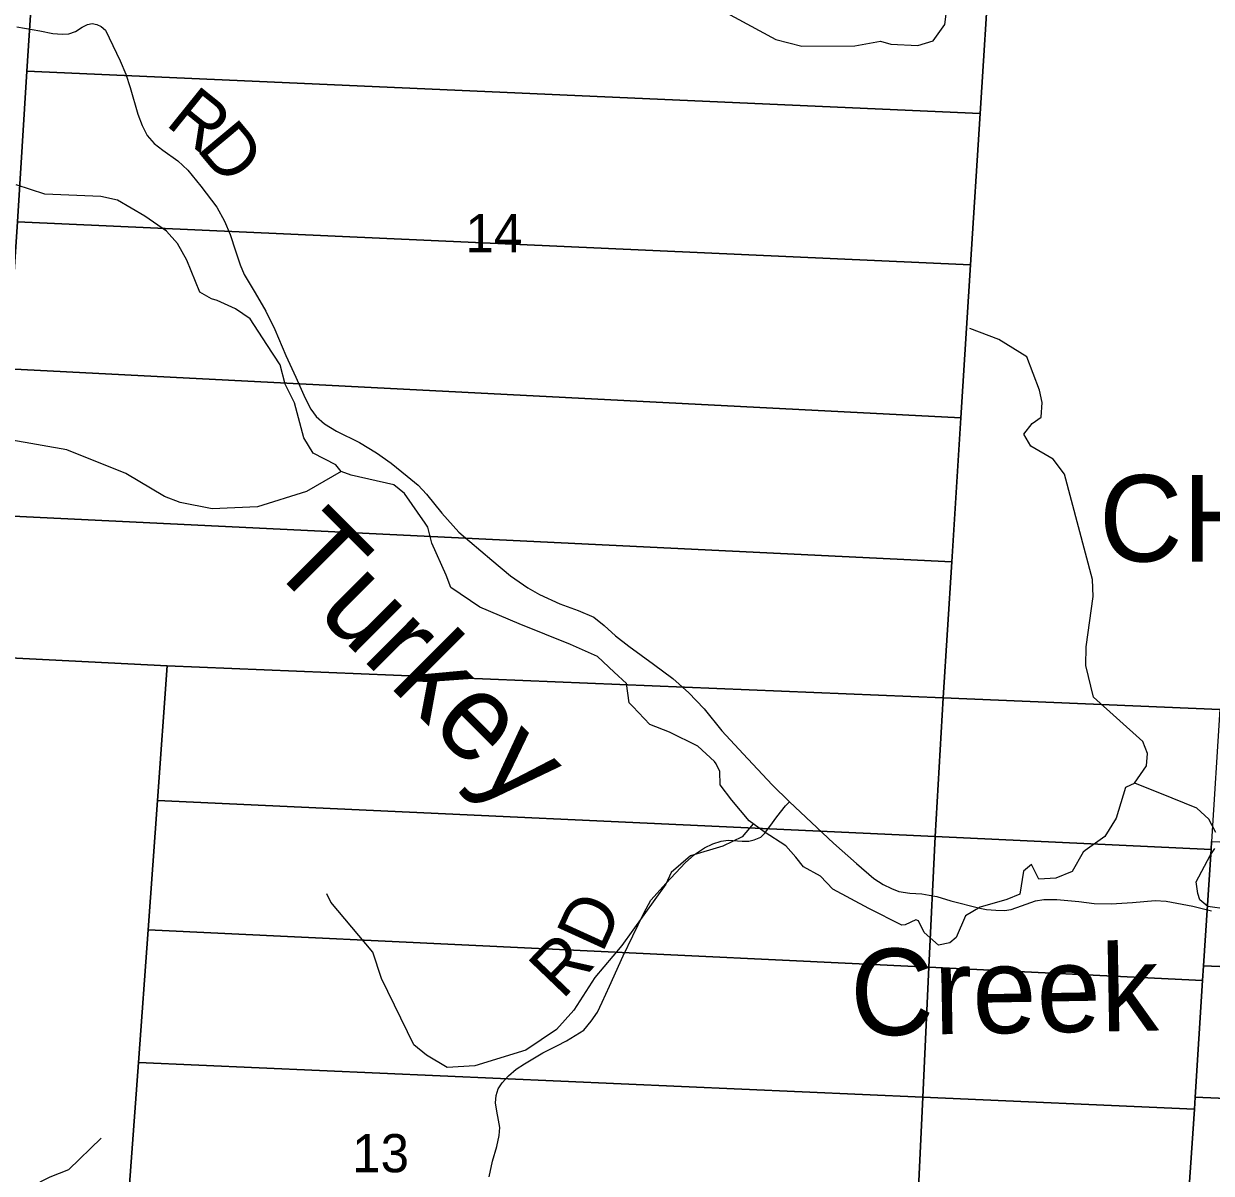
# Model space of a CAD drawing. Extents: x 1878108 to 2183446, y 146837 to 508383.
# Drawn here: x 2065694 to 2072564, y 342011 to 348659 of the extents above; entities that cross this region are included whole.
import ezdxf

# ---------------------------------------------------------------- set-up
doc = ezdxf.new("R2010")
doc.units = 0
for name, color, linetype in [('GM_X_Corporation_Text', 7, 'Continuous'), ('GM_X_Minor_River', 7, 'Continuous'), ('GM_X_Minor_River_Text', 7, 'Continuous'), ('GM_X_Section', 7, 'Continuous'), ('GM_X_Section_Text', 7, 'Continuous'), ('GM_X_Township_Road', 7, 'Continuous'), ('GM_X_Township_Road_Text', 7, 'Continuous')]:
    doc.layers.add(name, color=color, linetype=linetype)

msp = doc.modelspace()

# ---------------------------------------------------------------- linework, layer by layer
at = {"layer": 'GM_X_Minor_River'}
for points in [[(2069733.7, 348736.5), (2070045.5, 348568.4), (2070195.6, 348529.5), (2070502.1, 348532.1), (2070650.5, 348559.6), (2070710.5, 348541.2), (2070866.7, 348534.5), (2070955, 348560.2), (2071023.5, 348654.3), (2071050.4, 348869)], [(2067260.4, 346466.2), (2067206, 346574.2), (2067177.5, 346686.2), (2067099, 346804.1), (2067004.4, 346951.9), (2066918.2, 347011.6), (2066812.1, 347059.2), (2066780.1, 347069), (2066712, 347106.8), (2066637.2, 347292.8), (2066582.8, 347388.7), (2066518.5, 347460.5), (2066394.2, 347546.1), (2066236, 347639.5), (2066140, 347661.1), (2065816.4, 347673.6), (2065650.3, 347726.9)], [(2072119.3, 344267.1), (2072188.4, 344368.6), (2072195.6, 344438.8), (2072168.7, 344508.7), (2071883.1, 344764), (2071838.8, 344948), (2071839.5, 345056.2), (2071880, 345347.4), (2071876.9, 345445.6), (2071715.2, 346055.3), (2071650.1, 346140.8), (2071520.9, 346215.5), (2071480, 346285.2), (2071527.3, 346347.9), (2071579, 346384.6), (2071586, 346468.9), (2071571.1, 346540.9), (2071496.6, 346732.6), (2071335.1, 346833), (2071168.1, 346897.2)], [(2067530, 346070.8), (2067328.6, 345954.7), (2067045.2, 345865.2), (2066782.9, 345854.2), (2066598.1, 345890.1), (2066507.5, 345925.2), (2066283.5, 346059), (2065943.3, 346195.4), (2065624, 346251.9), (2065533.4, 346289), (2065271, 346448.4), (2065248.5, 346471.2)], [(2067530, 346070.8), (2067499.9, 346108.7), (2067367.7, 346176.2), (2067313.4, 346264.1), (2067260.4, 346466.2)], [(2072589.7, 343981.7), (2072549.4, 344059.6), (2072481.1, 344123.4), (2072337, 344180.8), (2072120.9, 344267.9), (2072067.1, 344241.6), (2072014, 344065), (2071948.6, 343958.5), (2071835.2, 343877.8), (2071823.3, 343867.8), (2071759.9, 343757.3), (2071664.2, 343718.8), (2071566.4, 343712.3), (2071524, 343796.2), (2071478.3, 343757.9), (2071456.9, 343625.6), (2071381.2, 343595.2), (2071227.6, 343550.3), (2071142, 343499.8), (2071088.6, 343375.4), (2071050.9, 343343.2), (2070985, 343330.8), (2070902.7, 343404.5), (2070870.5, 343470.5), (2070854.5, 343476.4), (2070792.7, 343448.1), (2070774.7, 343446), (2070582.5, 343543.2), (2070374.2, 343654.4), (2070303.9, 343730.2), (2070205.8, 343783.8), (2070159.6, 343839.6), (2070103.3, 343905.5), (2069977.1, 343985), (2069890.9, 344048.7), (2069790.5, 344168.4), (2069722.1, 344258.2), (2069721.7, 344334.3), (2069699.5, 344378.3), (2069689.5, 344392.3), (2069593.2, 344482), (2069429, 344563.3), (2069314.9, 344606.8), (2069216.5, 344710.5), (2069196.5, 344732.5), (2069179.9, 344844.6), (2069109.7, 344908.4), (2069013.4, 345000), (2068857.2, 345069.4), (2068559, 345188.2), (2068332.9, 345285.3), (2068164.5, 345398.6), (2068138.2, 345470.6), (2068055.4, 345654.6), (2068031, 345748.6), (2068016.9, 345770.6), (2067896.2, 345942.3), (2067834, 345992.1), (2067588.1, 346049), (2067530, 346070.8), (2067530, 346070.8)], [(2069913.8, 344031.7), (2069849.2, 343956.7), (2069737.7, 343903.3), (2069552, 343847), (2069439, 343751.5), (2069407.7, 343683), (2069153.5, 343329.2), (2068997.5, 343143), (2068875.5, 342955.1), (2068776.7, 342843.7), (2068597.8, 342723.4), (2068302.4, 342631.8), (2068144.2, 342623.9), (2068023.2, 342694.7), (2067950.3, 342754), (2067763.4, 343136.8), (2067713.5, 343290.5), (2067469.6, 343578.4), (2067446.5, 343626.8)], [(2072653.8, 343539.3), (2072543.8, 343554.8), (2072497.7, 343592.6), (2072485.6, 343628.6), (2072483.5, 343642.6), (2072477.2, 343696.7), (2072558.4, 343849.3), (2072584.2, 343889.5)], [(2064798.2, 339475.3), (2064818.6, 339981.8), (2064861.5, 340162.2), (2065176.6, 340769), (2065283.4, 340929.1), (2065352.1, 341069.3), (2065499.1, 341249.3), (2065543.6, 341337.5), (2065557.9, 341403.6), (2065582.9, 341632.3), (2065641.7, 341808.7), (2065732.4, 341932.8), (2065846.8, 341990.5), (2065955.2, 342032.1), (2066142.3, 342213.9)]]:
    msp.add_lwpolyline(points, dxfattribs=at)
at = {"layer": 'GM_X_Section'}
for points in [[(2071630.5, 349983.6), (2076880.8, 349683.9), (2076866.7, 349473.1), (2076805.5, 348566.4), (2076763.7, 347950.2), (2076689.4, 346949.7), (2076616.1, 345838.6), (2076512.2, 344478.8), (2072614, 344694.3), (2071013.5, 344761.7), (2071063, 345547.6), (2071115.7, 346380.1), (2071171.8, 347265.2), (2071227.3, 348141.2), (2071283.3, 349025.1), (2071330.9, 349777.5), (2071344.9, 349998.6)], [(2065766.6, 349241), (2065712.3, 348386.1), (2065656.9, 347512.9), (2065633.1, 347138.8), (2060116.6, 347430.3), (2060244.4, 349584.5), (2065773.5, 349349)], [(2065766.6, 349241), (2071283.3, 349025.1), (2071227.3, 348141.2), (2065712.3, 348386.1)], [(2071227.3, 348141.2), (2071171.8, 347265.2), (2065656.9, 347512.9), (2065712.3, 348386.1)], [(2065656.9, 347512.9), (2071171.8, 347265.2), (2071115.7, 346380.1), (2065603, 346664.6), (2065633.1, 347138.8)], [(2071115.7, 346380.1), (2071063, 345547.6), (2065549.1, 345815), (2065603, 346664.6)], [(2065549.1, 345815), (2071063, 345547.6), (2071013.5, 344761.7), (2066524.1, 344946.5), (2065497.3, 344999)], [(2066524.1, 344946.5), (2066467.3, 344166.6), (2066413, 343419.8), (2066357, 342651.9), (2066301.8, 341893.3), (2066247.1, 341132), (2066193.1, 340381.2), (2066136.7, 339596.4), (2065173.5, 339642), (2065497.3, 344999)], [(2071013.5, 344761.7), (2070965.8, 343958.4), (2066467.3, 344166.6), (2066524.1, 344946.5)], [(2071013.5, 344761.7), (2072614, 344694.3), (2072565.4, 343930.7), (2072562.5, 343884.5), (2070965.8, 343958.4)], [(2066467.3, 344166.6), (2070965.8, 343958.4), (2070930.5, 343202.9), (2066413, 343419.8)], [(2070965.8, 343958.4), (2072562.5, 343884.5), (2072519.6, 343211.3), (2072514.2, 343126.8), (2070930.5, 343202.9)], [(2072562.5, 343884.5), (2072565.4, 343930.7), (2076462, 343774.7), (2076410.5, 343050.4), (2072519.6, 343211.3)], [(2070930.5, 343202.9), (2070895.4, 342451.7), (2066357, 342651.9), (2066413, 343419.8)], [(2072514.2, 343126.8), (2072471.2, 342451), (2072466.8, 342382.3), (2070895.4, 342451.7), (2070930.5, 343202.9)], [(2072514.2, 343126.8), (2072519.6, 343211.3), (2076410.5, 343050.4), (2076356, 342285.1), (2072471.2, 342451)], [(2066357, 342651.9), (2070895.4, 342451.7), (2070859.5, 341682.3), (2066301.8, 341893.3)], [(2070895.4, 342451.7), (2072466.8, 342382.3), (2072420.5, 341706.8), (2072413.8, 341610.3), (2070859.5, 341682.3)], [(2072466.8, 342382.3), (2072471.2, 342451), (2076356, 342285.1), (2076304, 341554.2), (2072420.5, 341706.8)]]:
    msp.add_lwpolyline(points, close=True, dxfattribs=at)
at = {"layer": 'GM_X_Township_Road'}
for points in [[(2065654.1, 348641.2), (2065787.4, 348617.9), (2065861.4, 348603.1), (2065916.4, 348598.9), (2065953.4, 348601), (2065992.5, 348613.7), (2066030.6, 348639.1), (2066062.3, 348656), (2066089.8, 348661.3), (2066117.3, 348656), (2066141.6, 348644.4), (2066167, 348622.2), (2066250.5, 348445.6), (2066284.3, 348367.3), (2066309.7, 348290.2), (2066353, 348135.8), (2066379.5, 348071.3), (2066408, 348013.1), (2066448.2, 347966.6), (2066497.9, 347927.5), (2066584.6, 347867.2), (2066642.8, 347812.2), (2066718.9, 347720.3), (2066809.8, 347598.7), (2066855.3, 347518.3), (2066888.1, 347441.1), (2066918.7, 347347), (2066945.2, 347265.6), (2066969.5, 347208.5), (2067032.9, 347102.8), (2067094.2, 346998.1), (2067147.1, 346890.2), (2067209.5, 346740.1), (2067267.6, 346615.3), (2067321.6, 346494.8), (2067354.3, 346430.3), (2067386.1, 346388), (2067432.6, 346345.7), (2067502.4, 346302.4), (2067636.7, 346237.9), (2067735, 346177.6), (2067818.5, 346117.3), (2067912.6, 346042.3), (2067975, 345991.5), (2068023.6, 345938.6), (2068112.5, 345828.7), (2068210.8, 345718.7), (2068401.1, 345556.9), (2068510, 345467.1), (2068609.4, 345397.3), (2068677.1, 345358.2), (2068794.4, 345305.3), (2068901.3, 345265.6), (2068991.1, 345227.1), (2069051.4, 345178.4), (2069118, 345120.3), (2069194.1, 345058.9), (2069337.9, 344956.4), (2069447.9, 344871.8), (2069542, 344789.3), (2069583.2, 344746), (2069630.8, 344697.3), (2069733.3, 344570.5), (2069854.9, 344436.2), (2069968.1, 344316.7), (2070023.1, 344257.5), (2070124.6, 344159.1), (2070378.3, 343921.2), (2070511.5, 343802.8), (2070612, 343716.1), (2070664.9, 343681.2), (2070714.6, 343658), (2070755.8, 343641.1), (2070820.3, 343631.5), (2070890.1, 343627.3), (2070931.3, 343619.9), (2070975.7, 343611.4), (2071058.2, 343587.1), (2071224.2, 343543.8), (2071263.3, 343536.4), (2071318.3, 343532.1), (2071366.8, 343530.9), (2071407.1, 343536.4), (2071466.5, 343558), (2071547.7, 343586.1), (2071595.3, 343594.5), (2071671.4, 343594.5), (2071798.3, 343582.9), (2071886.1, 343572.3), (2071985.5, 343569.2), (2072108.1, 343577.6), (2072240.3, 343588.2), (2072303.4, 343584.4), (2072458.1, 343556.5), (2072565.8, 343529)], [(2068385.6, 341990.2), (2068406.2, 342080.5), (2068430.2, 342166.4), (2068444.3, 342230.6), (2068447.6, 342275.2), (2068440, 342318.7), (2068430.2, 342369.8), (2068423.6, 342418.7), (2068426.9, 342461.2), (2068438.9, 342499.2), (2068460.6, 342535.1), (2068498.7, 342575.4), (2068542.2, 342612.4), (2068590.1, 342645), (2068696.7, 342708.1), (2068778.2, 342748.3), (2068833.7, 342776.6), (2068934.9, 342839.7), (2068977.3, 342891.9), (2069013.2, 342943), (2069039.3, 343000.7), (2069081.7, 343093.1), (2069162.2, 343269.3), (2069216.6, 343384.6), (2069280.8, 343516.2), (2069321, 343591.3), (2069410.2, 343689.2), (2069521.1, 343806.7), (2069574.4, 343854.5), (2069632.1, 343892.6), (2069679.9, 343916.5), (2069728.9, 343932.8), (2069769.1, 343937.2), (2069850.7, 343931.7), (2069887.7, 343932.8), (2069920.3, 343940.4), (2069958.4, 343955.7), (2069981.2, 343977.4), (2069997.1, 344000), (2070010.1, 344016.4), (2070049.8, 344073.1), (2070099.8, 344136.2), (2070124.6, 344159.1)]]:
    msp.add_lwpolyline(points, dxfattribs=at)

# ---------------------------------------------------------------- texts
at = {"layer": 'GM_X_Corporation_Text'}
msp.add_text('CHESHIRE', height=500, rotation=0.00001, dxfattribs=at).set_placement((2071914.7, 345549.3))
at = {"layer": 'GM_X_Minor_River_Text'}
for s, height, rotation, p in [('Turkey', 499.95, 315.00489, (2067091.6, 345540.9)), ('Creek', 500, 0.99849, (2070479.3, 342806.1))]:
    msp.add_text(s, height=height, rotation=rotation, dxfattribs=at).set_placement(p)
at = {"layer": 'GM_X_Section_Text'}
for s, p in [('14', (2068249.5, 347338.2)), ('13', (2067593.9, 342017))]:
    msp.add_text(s, height=221, rotation=0.00001, dxfattribs=at).set_placement(p)
at = {"layer": 'GM_X_Township_Road_Text'}
for s, rotation, p in [('R', 321.16892, (2066506.9, 348078.1)), ('D', 309.85175, (2066687.7, 347934.5)), ('D', 65.50178, (2069040.4, 343278.4)), ('R', 46.21711, (2068809.3, 343011.2))]:
    msp.add_text(s, height=300, rotation=rotation, dxfattribs=at).set_placement(p)

doc.saveas('drawing.dxf')
